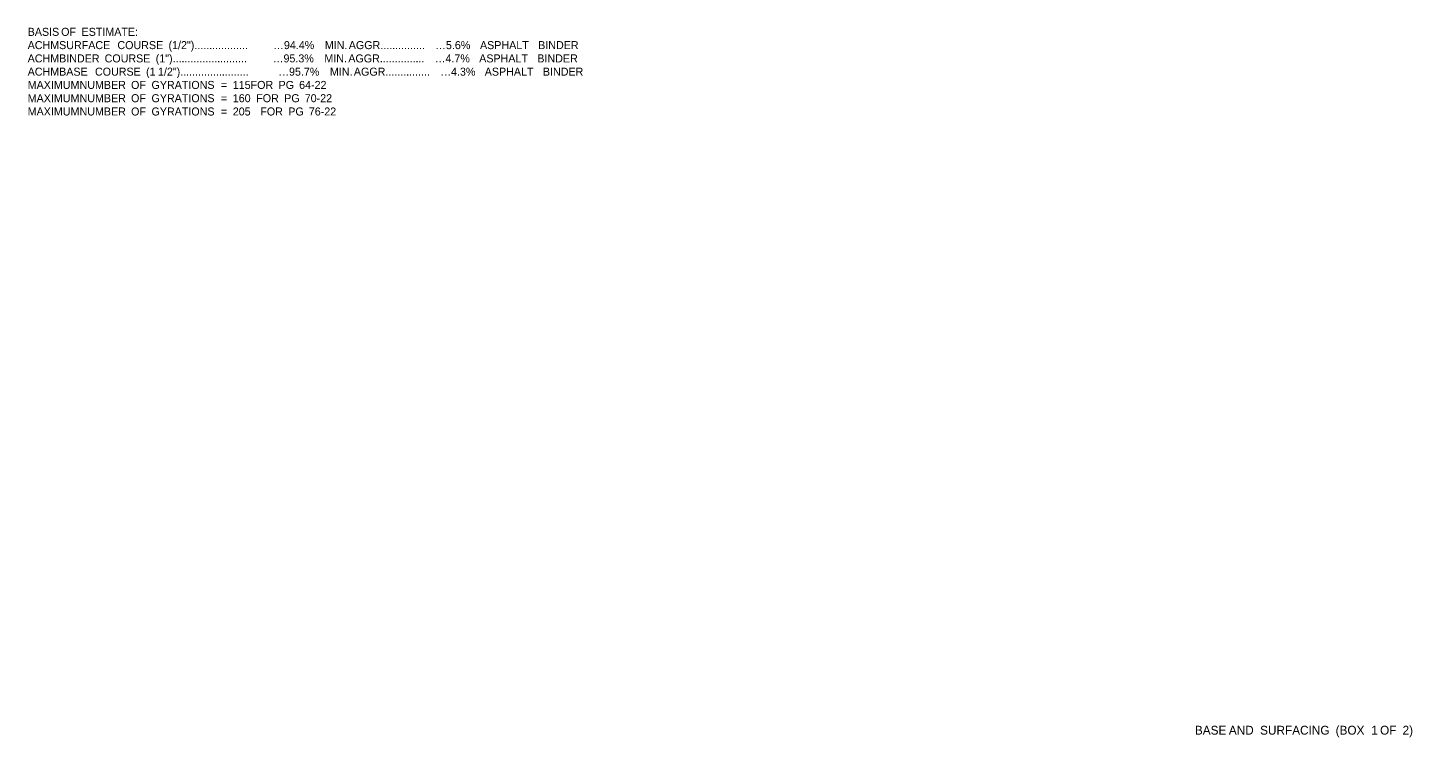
# Model space of a CAD drawing. Extents: x 1226590 to 1228573, y 151304 to 154224.
# Drawn here: x 1226591 to 1227456, y 152182 to 152625 of the extents above; entities that cross this region are included whole.
import ezdxf

# ---------------------------------------------------------------- set-up
doc = ezdxf.new("R2010")
doc.units = 0
doc.layers.add('R_Dimension', color=7, linetype='Continuous')

msp = doc.modelspace()

# ---------------------------------------------------------------- texts
at = {"layer": 'R_Dimension'}
for s, height, p in [('BASIS', 5, (1226591.25, 152620.33)), (' OF', 5, (1226610.3, 152620.33)), (' ESTIMATE:', 5, (1226623.06, 152620.33)), ('ACHM', 5, (1226591.25, 152612.04)), (' SURFACE', 5, (1226609.04, 152612.04)), (' COURSE', 5, (1226645.46, 152612.04)), (' (1/2")..................', 5, (1226677.39, 152612.04)), ('…94.4% ', 5, (1226744.67, 152612.04)), ('MIN. ', 5, (1226776.91, 152612.04)), ('AGGR...............', 5, (1226791.88, 152612.04)), ('…5.6% ', 5, (1226845.89, 152612.04)), ('ASPHALT ', 5, (1226873.88, 152612.04)), ('BINDER', 5, (1226910.22, 152612.04)), ('ACHM', 5, (1226591.25, 152603.75)), (' BINDER', 5, (1226609.04, 152603.75)), (' COURSE', 5, (1226637.47, 152603.75)), (' (1").........................', 5, (1226669.39, 152603.75)), ('…95.3% ', 5, (1226744.39, 152603.75)), ('MIN. ', 5, (1226776.64, 152603.75)), ('AGGR...............', 5, (1226791.6, 152603.75)), ('…4.7% ', 5, (1226845.62, 152603.75)), ('ASPHALT ', 5, (1226873.37, 152603.75)), ('BINDER', 5, (1226909.71, 152603.75)), ('ACHM', 5, (1226591.25, 152595.47)), (' BASE', 5, (1226609.04, 152595.47)), (' COURSE', 5, (1226631.44, 152595.47)), (' (1', 5, (1226663.37, 152595.47)), (' 1/2").......................', 5, (1226670.81, 152595.47)), ('…95.7% ', 5, (1226747.86, 152595.47)), ('MIN. ', 5, (1226780.1, 152595.47)), ('AGGR...............', 5, (1226795.06, 152595.47)), ('…4.3% ', 5, (1226849.08, 152595.47)), ('ASPHALT ', 5, (1226876.84, 152595.47)), ('BINDER', 5, (1226913.17, 152595.47)), ('MAXIMUM', 5, (1226591.25, 152587.18)), (' NUMBER', 5, (1226621.8, 152587.18)), (' OF', 5, (1226654, 152587.18)), (' GYRATIONS', 5, (1226666.76, 152587.18)), (' =', 5, (1226710.1, 152587.18)), (' 115', 5, (1226717.54, 152587.18)), (' FOR', 5, (1226728.69, 152587.18)), (' PG', 5, (1226746.17, 152587.18)), (' 64-22', 5, (1226759, 152587.18)), ('MAXIMUM', 5, (1226591.25, 152578.89)), (' NUMBER', 5, (1226621.8, 152578.89)), (' OF', 5, (1226654, 152578.89)), (' GYRATIONS', 5, (1226666.76, 152578.89)), (' =', 5, (1226710.1, 152578.89)), (' 160', 5, (1226717.54, 152578.89)), (' FOR', 5, (1226732.19, 152578.89)), (' PG', 5, (1226749.67, 152578.89)), (' 70-22', 5, (1226762.5, 152578.89)), ('MAXIMUM', 5, (1226591.25, 152570.6)), (' NUMBER', 5, (1226621.8, 152570.6)), (' OF', 5, (1226654, 152570.6)), (' GYRATIONS', 5, (1226666.76, 152570.6)), (' =', 5, (1226710.1, 152570.6)), (' 205', 5, (1226717.54, 152570.6)), (' FOR', 5, (1226734.75, 152570.6)), (' PG', 5, (1226752.23, 152570.6)), (' 76-22', 5, (1226765.06, 152570.6)), ('BASE', 5.509, (1227320.55, 152184.07)), (' AND', 5.509, (1227339.72, 152184.07)), (' SURFACING', 5.509, (1227359.25, 152184.07)), (' (BOX', 5.509, (1227406.44, 152184.07)), (' 1', 5.509, (1227428.7, 152184.07)), (' OF', 5.509, (1227434.21, 152184.07)), (' 2)', 5.509, (1227448.26, 152184.07))]:
    msp.add_text(s, height=height, dxfattribs=at).set_placement(p)

doc.saveas('drawing.dxf')
